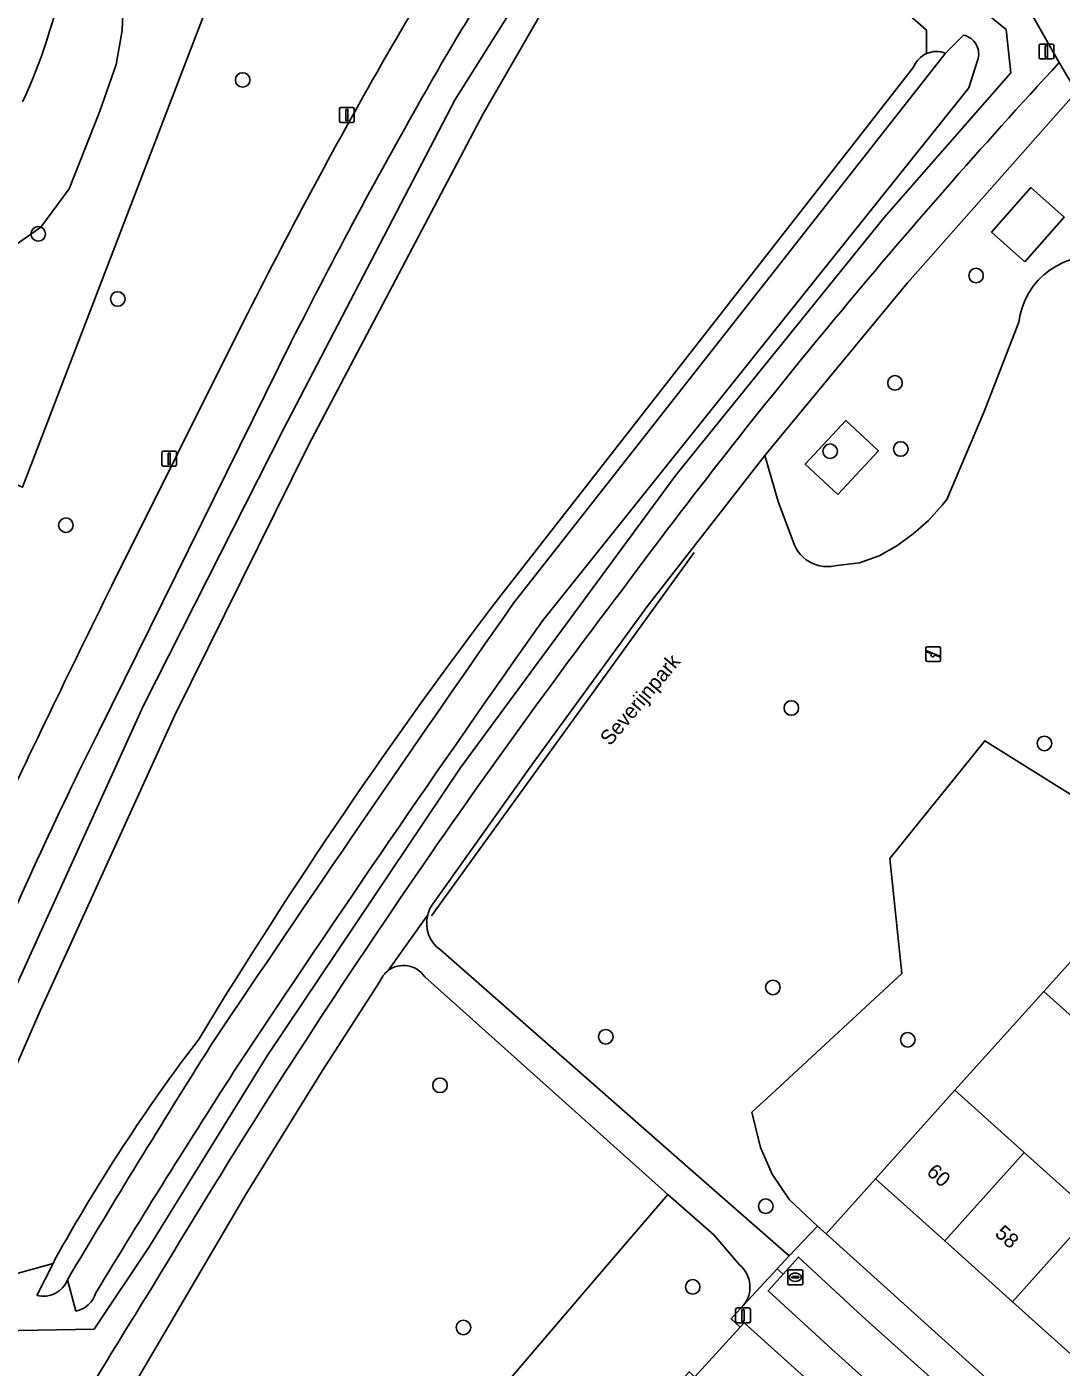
# Model space of a CAD drawing. Extents: x 159039 to 160102, y 381214 to 382524.
# Drawn here: x 159370.3 to 159439.8, y 382088.4 to 382178.5 of the extents above; entities that cross this region are included whole.
import ezdxf

# ---------------------------------------------------------------- set-up
doc = ezdxf.new("R2010")
doc.units = 0
for name, color, linetype in [('IMGEO_Boom', 7, 'Continuous'), ('IMGEO_Erf', 7, 'Continuous'), ('IMGEO_Fietspad_gesloten', 7, 'Continuous'), ('IMGEO_Fietspad_open', 7, 'Continuous'), ('IMGEO_Groenvoorziening', 7, 'Continuous'), ('IMGEO_Hek', 7, 'Continuous'), ('IMGEO_Lichtmast', 7, 'Continuous'), ('IMGEO_Meer_plas_ven_vijver', 7, 'Continuous'), ('IMGEO_Oever', 7, 'Continuous'), ('IMGEO_Openbare_ruimte_label', 7, 'Continuous'), ('IMGEO_Pand', 7, 'Continuous'), ('IMGEO_Pand_nummerreeks', 7, 'Continuous'), ('IMGEO_Rijbaan_lokaal_open', 7, 'Continuous'), ('IMGEO_Rioolput', 7, 'Continuous'), ('IMGEO_Speelvoorziening', 7, 'Continuous'), ('IMGEO_Voetpad_gesloten', 7, 'Continuous'), ('IMGEO_Voetpad_open', 7, 'Continuous'), ('IMGEO_Waterloop', 7, 'Continuous')]:
    doc.layers.add(name, color=color, linetype=linetype)

msp = doc.modelspace()

# ---------------------------------------------------------------- linework, layer by layer
at = {"layer": 'IMGEO_Boom'}
for centre in [(159384.797, 382174.971), (159371.055, 382164.623), (159434.102, 382161.823), (159376.399, 382160.248), (159428.651, 382154.608), (159429.041, 382150.164), (159424.293, 382150.014), (159372.914, 382145.045), (159421.684, 382132.754), (159438.698, 382130.372), (159420.442, 382113.976), (159409.208, 382110.658), (159429.512, 382110.451), (159398.062, 382107.391), (159419.967, 382099.266), (159415.053, 382093.845), (159399.639, 382091.116)]:
    msp.add_circle(centre, 0.489, dxfattribs=at)
at = {"layer": 'IMGEO_Erf'}
for points in [[(159447.332, 382104.853), (159444.401, 382107.483), (159446.182, 382109.469), (159442.855, 382112.454), (159441.607, 382111.063), (159438.669, 382113.699), (159432.686, 382107.057), (159437.336, 382102.884), (159441.895, 382098.793), (159446.455, 382094.7), (159451.014, 382090.609), (159455.662, 382086.437), (159450.321, 382080.486), (159445.673, 382084.658), (159441.114, 382088.749), (159436.554, 382092.841), (159431.994, 382096.933), (159427.345, 382101.105), (159424.019, 382097.413), (159447.998, 382075.782)], [(159442.459, 382069.847), (159418.503, 382091.427), (159418.239, 382091.137), (159415.202, 382087.803), (159419.558, 382083.893), (159424.207, 382079.721), (159428.857, 382075.549), (159433.506, 382071.376), (159438.245, 382067.123), (159432.861, 382061.124), (159428.122, 382065.377), (159423.473, 382069.55), (159418.824, 382073.722), (159414.174, 382077.895)]]:
    msp.add_lwpolyline(points, dxfattribs=at)
at = {"layer": 'IMGEO_Fietspad_gesloten'}
for points in [[(159384.841, 382158.7), (159376.008, 382140.992)], [(159375.118, 382131.186), (159388.062, 382157.36)]]:
    msp.add_lwpolyline(points, dxfattribs=at)
for centre, radius, start, end in [((159545.656, 382089.742), 174.37, 146.13883, 150.3364), ((159526.85, 382101.276), 148.839, 145.75643, 150.62479), ((159732.91, 381983.231), 389.797, 150.35413, 153.24633), ((159715.243, 381992.618), 366.316, 150.26889, 153.27384), ((160147.437, 381758.607), 861, 153.633098, 154.915239), ((159654.193, 381992.43), 311.667, 153.56354, 157.09927)]:
    msp.add_arc(centre, radius, start, end, dxfattribs=at)
at = {"layer": 'IMGEO_Fietspad_open'}
msp.add_lwpolyline([(159434.445, 382185.404), (159439.697, 382176.141), (159440.858, 382174.182)], dxfattribs=at)
at = {"layer": 'IMGEO_Groenvoorziening'}
for points in [[(159392.579, 382206.409), (159369.999, 382147.594), (159365.79, 382149.372), (159363.767, 382150.226), (159359.537, 382139.442), (159361.581, 382138.535), (159365.25, 382136.906), (159366.503, 382136.368), (159366.892, 382135.171), (159361.663, 382115.379)], [(159376.846, 382182.174), (159376.686, 382178.287), (159376.302, 382176.015), (159375.202, 382172.877), (159373.142, 382167.657), (159371.224, 382165.066), (159368.968, 382163.485), (159363.767, 382150.226), (159365.79, 382149.372), (159369.999, 382147.594), (159392.579, 382206.409)], [(159422.353, 382190.549), (159422.734, 382190.305), (159422.983, 382190.468), (159424.514, 382188.415), (159427.144, 382183.833), (159429.09, 382182.451), (159432.379, 382180.645), (159434.583, 382179.615), (159436.124, 382178.366), (159436.429, 382175.447), (159427.914, 382165.716), (159413.925, 382148.417), (159399.408, 382128.719), (159386.451, 382109.386), (159378.514, 382096.541), (159374.803, 382091.012), (159368.466, 382090.901), (159366.281, 382091.313), (159365.922, 382092.134), (159365.812, 382091.888), (159364.063, 382092.583), (159364.104, 382092.669)], [(159370.949, 382093.26), (159372.05, 382095.426), (159367.168, 382094.07), (159365.662, 382092.326), (159365.957, 382092.214), (159365.922, 382092.134), (159366.281, 382091.313), (159368.466, 382090.901), (159374.803, 382091.012), (159378.514, 382096.541), (159386.451, 382109.386), (159399.408, 382128.719), (159413.925, 382148.417), (159427.914, 382165.716), (159436.429, 382175.447), (159436.124, 382178.366), (159434.583, 382179.615), (159432.379, 382180.645), (159429.09, 382182.451), (159427.144, 382183.833), (159424.514, 382188.415), (159424.287, 382188.282), (159422.734, 382190.305), (159422.353, 382190.549)], [(159422.565, 382189.431), (159423.42, 382188.491), (159422.888, 382187.383), (159423.674, 382185.224), (159425.964, 382182.543), (159430.762, 382178.322), (159430.78, 382176.745)], [(159408.268, 382188.263), (159399.088, 382173.666), (159387.535, 382151.506), (159378.119, 382132.921), (159369.246, 382113.396), (159362.92, 382093.152), (159364.104, 382092.669), (159364.204, 382092.878), (159364.739, 382092.675), (159365.059, 382098.418), (159371.182, 382112.41), (159380.224, 382132.238), (159389.22, 382150.415), (159400.964, 382172.686), (159409.272, 382187.122)], [(159364.104, 382092.669), (159362.92, 382093.152), (159369.246, 382113.396), (159378.119, 382132.921), (159387.535, 382151.506), (159399.088, 382173.666), (159408.268, 382188.263)], [(159439.697, 382176.141), (159434.445, 382185.404)], [(159433.268, 382177.987), (159432.043, 382176.774), (159403.013, 382139.809)], [(159432.043, 382176.774), (159433.268, 382177.987)], [(159403.013, 382139.809), (159432.043, 382176.774)], [(159404.959, 382138.622), (159433.607, 382174.444), (159434.204, 382176.286)], [(159434.204, 382176.286), (159433.607, 382174.444), (159404.959, 382138.622)], [(159429.907, 382175.831), (159402.148, 382140.325)], [(159440.858, 382174.182), (159429.499, 382161.337), (159419.901, 382149.722), (159420.807, 382146.642), (159421.896, 382143.703), (159422.011, 382143.477), (159422.148, 382143.264), (159422.308, 382143.066), (159422.487, 382142.886), (159422.684, 382142.726), (159422.896, 382142.588), (159423.122, 382142.472), (159423.359, 382142.381), (159423.603, 382142.314), (159423.854, 382142.274), (159424.107, 382142.26), (159424.361, 382142.273), (159424.611, 382142.312), (159424.747, 382142.345), (159426.257, 382142.505), (159427.588, 382142.981), (159428.774, 382143.66), (159429.882, 382144.459), (159430.901, 382145.37), (159431.819, 382146.382), (159432.128, 382146.776), (159434.651, 382152.693), (159436.985, 382158.687)], [(159436.985, 382158.687), (159437.074, 382159.206), (159437.217, 382159.713), (159437.413, 382160.202), (159437.658, 382160.668), (159437.951, 382161.106), (159438.288, 382161.51), (159438.665, 382161.878), (159439.079, 382162.203), (159439.524, 382162.484), (159439.996, 382162.717), (159440.491, 382162.899), (159440.862, 382162.999), (159442.188, 382163.506), (159443.56, 382163.872), (159444.962, 382164.092), (159446.38, 382164.165), (159447.216, 382164.138)], [(159439.996, 382162.717), (159439.524, 382162.484), (159439.079, 382162.203), (159438.665, 382161.878), (159438.288, 382161.51), (159437.951, 382161.106), (159437.658, 382160.668), (159437.413, 382160.202), (159437.217, 382159.713), (159437.074, 382159.206), (159436.985, 382158.687), (159434.651, 382152.693), (159432.128, 382146.776), (159431.819, 382146.382), (159430.901, 382145.37), (159429.882, 382144.459), (159428.774, 382143.66), (159427.588, 382142.981), (159426.257, 382142.505), (159424.747, 382142.345), (159424.611, 382142.312), (159424.361, 382142.273), (159424.107, 382142.26), (159423.854, 382142.274), (159423.603, 382142.314), (159423.359, 382142.381), (159423.122, 382142.472), (159422.896, 382142.588), (159422.684, 382142.726), (159422.487, 382142.886), (159422.308, 382143.066), (159422.148, 382143.264), (159422.011, 382143.477), (159421.896, 382143.703), (159420.807, 382146.642), (159419.901, 382149.722), (159411.987, 382139.576), (159404.234, 382128.932), (159397.604, 382119.622)], [(159376.008, 382140.992), (159384.841, 382158.7)], [(159388.062, 382157.36), (159375.118, 382131.186)], [(159398.091, 382116.491), (159414.906, 382101.741), (159421.535, 382095.926), (159423.442, 382097.934), (159421.556, 382099.695), (159420.403, 382101.425), (159419.602, 382103.218), (159419.033, 382105.59), (159420.624, 382107.039), (159429.12, 382114.911), (159428.315, 382122.632), (159434.692, 382130.55), (159440.797, 382126.746), (159447.77, 382133.461), (159453.41, 382139.902)], [(159440.797, 382126.746), (159434.692, 382130.55), (159428.315, 382122.632), (159429.12, 382114.911), (159420.624, 382107.039), (159419.033, 382105.59), (159419.602, 382103.218), (159420.403, 382101.425), (159421.556, 382099.695), (159423.442, 382097.934), (159424.019, 382097.413), (159427.345, 382101.105), (159432.686, 382107.057), (159438.669, 382113.699), (159440.485, 382115.723)], [(159408.66, 382094.544), (159413.377, 382100.065), (159397.037, 382114.689)], [(159394.028, 382114.374), (159390.166, 382108.397), (159385.031, 382100.107), (159373.992, 382081.27), (159377.887, 382077.878), (159385.857, 382070.936), (159387.365, 382069.622), (159408.66, 382094.544)], [(159418.2, 382095.331), (159416.462, 382097.35), (159413.377, 382100.065), (159408.66, 382094.544), (159387.365, 382069.622), (159385.857, 382070.936), (159378.221, 382062.169), (159386.063, 382055.21), (159386.52, 382055.672), (159389.076, 382058.583), (159394.457, 382064.578), (159400.284, 382071.006), (159402.2, 382073.142), (159403.989, 382075.135), (159403.541, 382075.537), (159405.385, 382077.591)], [(159372.176, 382095.675), (159372.05, 382095.426), (159370.949, 382093.26)], [(159373.024, 382094.328), (159373.57, 382092.204)], [(159373.57, 382092.204), (159373.024, 382094.328)], [(159405.385, 382077.591), (159409.437, 382082.146), (159414.821, 382088.145), (159415.202, 382087.803), (159418.239, 382091.137), (159417.632, 382091.692), (159418.453, 382092.583)]]:
    msp.add_lwpolyline(points, dxfattribs=at)
for points in [[(159437.391, 382162.754), (159440.035, 382165.752), (159437.786, 382167.734), (159435.143, 382164.737)], [(159437.391, 382162.754), (159435.143, 382164.737), (159437.786, 382167.734), (159440.035, 382165.752)], [(159424.805, 382147.11), (159427.536, 382150.043), (159425.337, 382152.089), (159422.607, 382149.155)], [(159424.805, 382147.11), (159422.607, 382149.155), (159425.337, 382152.089), (159427.536, 382150.043)]]:
    msp.add_lwpolyline(points, close=True, dxfattribs=at)
for centre, radius, start, end in [((159545.656, 382089.742), 174.37, 146.13883, 150.3364), ((159526.85, 382101.276), 148.839, 145.75643, 150.62479), ((159432.983, 382176.722), 1.297, 340.34802, 77.29684), ((159432.983, 382176.722), 1.297, 340.34802, 77.29684), ((159431.448, 382175.233), 1.653, 113.8441, 158.78457), ((159431.447, 382175.233), 1.652, 68.83662, 113.79407), ((159431.447, 382175.233), 1.652, 68.83662, 113.79407), ((159732.91, 381983.231), 389.797, 150.35413, 153.24633), ((159752.486, 381886.865), 426.049, 137.23651, 143.42294), ((159715.243, 381992.618), 366.316, 150.26889, 153.27384), ((160147.437, 381758.607), 861, 153.633098, 154.915239), ((159813.221, 381835.149), 505.669, 142.81805, 149.21492), ((159674.386, 381933.239), 342.05, 142.74049, 148.7828), ((160854.298, 381124.423), 1771.225, 145.0216, 146.188315), ((160854.298, 381124.423), 1771.225, 145.0216, 146.188315), ((160450.54, 381400.124), 1280.085, 144.766282, 146.385082), ((160450.54, 381400.124), 1280.085, 144.766282, 146.385082), ((159654.193, 381992.43), 311.667, 153.56354, 157.09927), ((159399.406, 382118.293), 2.239, 143.58139, 165.40474), ((159399.392, 382118.296), 2.225, 165.38831, 234.21973), ((159395.613, 382113.748), 1.704, 127.40157, 158.45674), ((159395.615, 382113.748), 1.705, 33.4951, 127.43671), ((159478.564, 382036.832), 121.577, 142.69292, 151.05308), ((159941.525, 381757.41), 660.838, 147.749459, 149.347191), ((159941.525, 381757.41), 660.838, 147.749459, 149.347191), ((159889.716, 381782.72), 601.291, 147.160781, 148.885497), ((159889.716, 381782.72), 601.291, 147.160781, 148.885497), ((159416.94, 382093.829), 1.96, 320.51924, 50.0012), ((159702.63, 381890.619), 382.375, 147.87389, 151.49088), ((159371.375, 382094.983), 1.774, 256.11767, 338.35198), ((159371.375, 382094.983), 1.774, 256.11767, 338.35198), ((159373.191, 382093.987), 1.823, 281.99129, 342.44267), ((159373.191, 382093.987), 1.823, 281.99129, 342.44267)]:
    msp.add_arc(centre, radius, start, end, dxfattribs=at)
at = {"layer": 'IMGEO_Hek'}
msp.add_lwpolyline([(159397.488, 382118.797), (159415.14, 382143.214)], dxfattribs=at)
at = {"layer": 'IMGEO_Lichtmast'}
for p, q in [((159438.337, 382176.487), (159438.337, 382177.287)), ((159438.337, 382177.287), (159438.337, 382176.487)), ((159438.437, 382177.387), (159439.227, 382177.387)), ((159439.227, 382177.387), (159438.437, 382177.387)), ((159439.327, 382177.287), (159439.327, 382176.487)), ((159439.327, 382176.487), (159439.327, 382177.287)), ((159439.227, 382176.387), (159438.437, 382176.387)), ((159438.437, 382176.387), (159439.227, 382176.387)), ((159391.307, 382172.221), (159391.307, 382173.021)), ((159391.307, 382173.021), (159391.307, 382172.221)), ((159391.407, 382173.121), (159392.197, 382173.121)), ((159392.197, 382173.121), (159391.407, 382173.121)), ((159392.297, 382173.021), (159392.297, 382172.221)), ((159392.297, 382172.221), (159392.297, 382173.021)), ((159392.197, 382172.121), (159391.407, 382172.121)), ((159391.407, 382172.121), (159392.197, 382172.121)), ((159379.363, 382149.118), (159379.363, 382149.918)), ((159379.363, 382149.918), (159379.363, 382149.118)), ((159379.463, 382150.018), (159380.253, 382150.018)), ((159380.253, 382150.018), (159379.463, 382150.018)), ((159380.353, 382149.918), (159380.353, 382149.118)), ((159380.353, 382149.118), (159380.353, 382149.918)), ((159380.253, 382149.018), (159379.463, 382149.018)), ((159379.463, 382149.018), (159380.253, 382149.018)), ((159417.939, 382091.526), (159417.939, 382092.326)), ((159417.939, 382092.326), (159417.939, 382091.526)), ((159418.039, 382092.426), (159418.829, 382092.426)), ((159418.829, 382092.426), (159418.039, 382092.426)), ((159418.929, 382092.326), (159418.929, 382091.526)), ((159418.929, 382091.526), (159418.929, 382092.326)), ((159418.829, 382091.426), (159418.039, 382091.426)), ((159418.039, 382091.426), (159418.829, 382091.426))]:
    msp.add_line(p, q, dxfattribs=at)
for points in [[(159438.757, 382177.262), (159438.907, 382177.262), (159438.907, 382176.512), (159438.757, 382176.512), (159438.757, 382177.262)], [(159391.727, 382172.996), (159391.877, 382172.996), (159391.877, 382172.246), (159391.727, 382172.246), (159391.727, 382172.996)], [(159379.783, 382149.893), (159379.933, 382149.893), (159379.933, 382149.143), (159379.783, 382149.143), (159379.783, 382149.893)], [(159418.359, 382092.301), (159418.509, 382092.301), (159418.509, 382091.551), (159418.359, 382091.551), (159418.359, 382092.301)]]:
    msp.add_lwpolyline(points, dxfattribs=at)
for centre, start, end in [((159438.437, 382177.287), 90, 180), ((159438.437, 382177.287), 90, 180), ((159439.227, 382177.287), 0, 90), ((159439.227, 382177.287), 360, 90), ((159438.437, 382176.487), 180, 270), ((159438.437, 382176.487), 180, 270), ((159439.227, 382176.487), 270, 0), ((159439.227, 382176.487), 270, 0), ((159391.407, 382173.021), 90, 180), ((159391.407, 382173.021), 90, 180), ((159392.197, 382173.021), 0, 90), ((159392.197, 382173.021), 360, 90), ((159391.407, 382172.221), 180, 270), ((159391.407, 382172.221), 180, 270), ((159392.197, 382172.221), 270, 0), ((159392.197, 382172.221), 270, 0), ((159379.463, 382149.918), 90, 180), ((159379.463, 382149.918), 90, 180), ((159380.253, 382149.918), 0, 90), ((159380.253, 382149.918), 360, 90), ((159379.463, 382149.118), 180, 270), ((159379.463, 382149.118), 180, 270), ((159380.253, 382149.118), 270, 0), ((159380.253, 382149.118), 270, 0), ((159418.039, 382092.326), 90, 180), ((159418.039, 382092.326), 90, 180), ((159418.829, 382092.326), 0, 90), ((159418.829, 382092.326), 360, 90), ((159418.039, 382091.526), 180, 270), ((159418.039, 382091.526), 180, 270), ((159418.829, 382091.526), 270, 0), ((159418.829, 382091.526), 270, 0)]:
    msp.add_arc(centre, 0.1, start, end, dxfattribs=at)
at = {"layer": 'IMGEO_Meer_plas_ven_vijver'}
for points in [[(159430.78, 382176.745), (159430.762, 382178.322), (159425.964, 382182.543), (159423.674, 382185.224), (159422.888, 382187.383), (159423.42, 382188.491), (159422.565, 382189.431)], [(159409.272, 382187.122), (159400.964, 382172.686), (159389.22, 382150.415), (159380.224, 382132.238), (159371.182, 382112.41), (159365.059, 382098.418), (159364.739, 382092.675), (159365.662, 382092.326), (159367.168, 382094.07), (159372.05, 382095.426), (159372.176, 382095.675)], [(159402.148, 382140.325), (159429.907, 382175.831)]]:
    msp.add_lwpolyline(points, dxfattribs=at)
for centre, radius, start, end in [((159431.448, 382175.233), 1.653, 113.8441, 158.78457), ((159674.386, 381933.239), 342.05, 142.74049, 148.7828), ((159478.564, 382036.832), 121.577, 142.69292, 151.05308)]:
    msp.add_arc(centre, radius, start, end, dxfattribs=at)
at = {"layer": 'IMGEO_Oever'}
msp.add_lwpolyline([(159329.64, 382062.981), (159336.5, 382081.036), (159338.599, 382083.068), (159340.207, 382084.766), (159341.09, 382085.551), (159342.397, 382086.714), (159343.395, 382090.494), (159343.294, 382091.297), (159343.198, 382092.049), (159342.522, 382092.718), (159341.643, 382093.428), (159341.595, 382094.275), (159351.487, 382118.919), (159359.537, 382139.442), (159363.767, 382150.226), (159368.968, 382163.485), (159371.224, 382165.066), (159373.142, 382167.657), (159375.202, 382172.877), (159376.302, 382176.015), (159376.686, 382178.287), (159376.846, 382182.174)], dxfattribs=at)
msp.add_arc((159335.714, 382189.399), 37.792, 335.1341, 348.80944, dxfattribs=at)
at = {"layer": 'IMGEO_Pand'}
for points in [[(159440.485, 382115.723), (159438.669, 382113.699), (159441.607, 382111.063), (159442.855, 382112.454), (159443.423, 382113.087)], [(159437.336, 382102.884), (159432.686, 382107.057), (159427.345, 382101.105), (159431.994, 382096.933)], [(159437.336, 382102.884), (159431.994, 382096.933), (159436.554, 382092.841), (159441.895, 382098.793)], [(159441.895, 382098.793), (159436.554, 382092.841), (159441.114, 382088.749), (159446.455, 382094.7)]]:
    msp.add_lwpolyline(points, close=True, dxfattribs=at)
at = {"layer": 'IMGEO_Rijbaan_lokaal_open'}
msp.add_lwpolyline([(159426.476, 382091.859), (159422.172, 382095.85), (159421.139, 382094.706), (159420.122, 382093.578), (159424.405, 382089.668), (159432.474, 382082.409), (159445.513, 382070.713), (159447.544, 382072.913), (159439.286, 382080.355)], close=True, dxfattribs=at)
at = {"layer": 'IMGEO_Rioolput'}
for p, q in [((159421.448, 382094.064), (159421.448, 382094.916)), ((159421.523, 382094.99), (159422.375, 382094.99)), ((159421.936, 382094.77), (159421.961, 382094.77)), ((159422.449, 382094.916), (159422.449, 382094.064)), ((159422.375, 382093.99), (159421.523, 382093.99)), ((159421.707, 382094.484), (159421.707, 382094.496)), ((159422.145, 382094.447), (159421.747, 382094.447)), ((159421.75, 382094.533), (159422.148, 382094.533)), ((159421.959, 382094.21), (159421.934, 382094.21)), ((159422.191, 382094.496), (159422.191, 382094.484))]:
    msp.add_line(p, q, dxfattribs=at)
for points in [[(159421.448, 382094.064), (159421.448, 382094.916)], [(159421.523, 382094.99), (159422.375, 382094.99)], [(159422.449, 382094.916), (159422.449, 382094.064)], [(159422.375, 382093.99), (159421.523, 382093.99)]]:
    msp.add_lwpolyline(points, dxfattribs=at)
for centre, radius, start, end in [((159421.525, 382094.914), 0.0765, 91.55205, 178.44795), ((159421.525, 382094.914), 0.0765, 91.55205, 178.44795), ((159422.373, 382094.914), 0.0765, 1.55205, 88.44795), ((159422.373, 382094.914), 0.0765, 1.55205, 88.44795), ((159421.525, 382094.066), 0.0765, 181.55205, 268.44795), ((159421.525, 382094.066), 0.0765, 181.55205, 268.44795), ((159421.747, 382094.493), 0.0403, 85.87752, 175.75265), ((159421.744, 382094.483), 0.0366, 178.93798, 274.71019), ((159422.148, 382094.49), 0.043, 264.86636, 352.45326), ((159422.152, 382094.495), 0.0386, 1.73085, 96.63898), ((159422.373, 382094.066), 0.0765, 271.55205, 358.44795), ((159422.373, 382094.066), 0.0765, 271.55205, 358.44795)]:
    msp.add_arc(centre, radius, start, end, dxfattribs=at)
for centre, major_axis, ratio, start_param, end_param in [((159421.935, 382094.49), (-0.387, 0.002), 0.722429, 4.712389, 7.853982), ((159421.96, 382094.49), (-0.39, 0.002), 0.717154, 1.570796, 4.712389)]:
    msp.add_ellipse(centre, major_axis=major_axis, ratio=ratio, start_param=start_param, end_param=end_param, dxfattribs=at)
at = {"layer": 'IMGEO_Speelvoorziening'}
for p, q in [((159430.728, 382135.975), (159430.728, 382136.775)), ((159430.728, 382136.775), (159430.728, 382135.975)), ((159431.111, 382136.403), (159430.772, 382136.54)), ((159430.797, 382136.6), (159431.673, 382136.247)), ((159430.828, 382136.875), (159431.618, 382136.875)), ((159431.618, 382136.875), (159430.828, 382136.875)), ((159431.649, 382136.187), (159431.309, 382136.324)), ((159431.718, 382136.775), (159431.718, 382135.975)), ((159431.718, 382135.975), (159431.718, 382136.775)), ((159431.618, 382135.875), (159430.828, 382135.875)), ((159430.828, 382135.875), (159431.618, 382135.875))]:
    msp.add_line(p, q, dxfattribs=at)
for centre, radius, start, end in [((159430.828, 382136.775), 0.1, 90, 180), ((159430.828, 382136.775), 0.1, 90, 180), ((159430.785, 382136.57), 0.0327, 68.07798, 248.07798), ((159431.19, 382136.313), 0.12, 130.99278, 5.16318), ((159431.618, 382136.775), 0.1, 0, 90), ((159431.618, 382136.775), 0.1, 360, 90), ((159431.661, 382136.217), 0.0327, 248.07798, 68.07798), ((159430.828, 382135.975), 0.1, 180, 270), ((159430.828, 382135.975), 0.1, 180, 270), ((159431.618, 382135.975), 0.1, 270, 0), ((159431.618, 382135.975), 0.1, 270, 0)]:
    msp.add_arc(centre, radius, start, end, dxfattribs=at)
at = {"layer": 'IMGEO_Voetpad_gesloten'}
for points in [[(159397.604, 382119.622), (159404.234, 382128.932), (159411.987, 382139.576), (159419.901, 382149.722), (159429.499, 382161.337), (159440.858, 382174.182), (159439.697, 382176.141)], [(159394.578, 382115.102), (159397.239, 382118.857)], [(159397.239, 382118.857), (159394.578, 382115.102)], [(159418.453, 382092.583), (159420.742, 382095.065), (159421.535, 382095.926), (159414.906, 382101.741), (159398.091, 382116.491)], [(159397.037, 382114.689), (159413.377, 382100.065), (159416.462, 382097.35), (159418.2, 382095.331)], [(159368.975, 382072.218), (159373.992, 382081.27), (159385.031, 382100.107), (159390.166, 382108.397), (159394.028, 382114.374)]]:
    msp.add_lwpolyline(points, dxfattribs=at)
for centre, radius, start, end in [((159752.486, 381886.865), 426.049, 137.23651, 143.42294), ((159813.221, 381835.149), 505.669, 142.81805, 149.21492), ((159399.406, 382118.293), 2.239, 143.58139, 165.40474), ((159399.392, 382118.296), 2.225, 165.38831, 234.21973), ((159395.613, 382113.748), 1.704, 127.40157, 158.45674), ((159395.615, 382113.748), 1.705, 33.4951, 127.43671), ((159416.94, 382093.829), 1.96, 320.51924, 50.0012), ((159702.63, 381890.619), 382.375, 147.87389, 151.49088)]:
    msp.add_arc(centre, radius, start, end, dxfattribs=at)
at = {"layer": 'IMGEO_Voetpad_open'}
for points in [[(159424.019, 382097.413), (159423.442, 382097.934), (159421.535, 382095.926), (159420.742, 382095.065), (159421.139, 382094.706), (159422.172, 382095.85), (159426.476, 382091.859), (159439.286, 382080.355), (159447.544, 382072.913), (159449.93, 382075.598)], [(159447.998, 382075.782), (159424.019, 382097.413)], [(159432.474, 382082.409), (159424.405, 382089.668), (159420.122, 382093.578), (159421.139, 382094.706), (159420.742, 382095.065), (159418.453, 382092.583), (159417.632, 382091.692), (159418.239, 382091.137), (159418.503, 382091.427), (159442.459, 382069.847)]]:
    msp.add_lwpolyline(points, dxfattribs=at)
at = {"layer": 'IMGEO_Waterloop'}
msp.add_arc((159335.714, 382189.399), 37.792, 335.1341, 348.80944, dxfattribs=at)

# ---------------------------------------------------------------- texts
at = {"layer": 'IMGEO_Openbare_ruimte_label'}
msp.add_text('Severijnpark', height=1, rotation=49.90832, dxfattribs=at).set_placement((159409.498, 382130.158))
at = {"layer": 'IMGEO_Pand_nummerreeks'}
for s, p in [('60', (159430.713, 382101.468)), ('58', (159435.308, 382097.345))]:
    msp.add_text(s, height=1, rotation=318.09473, dxfattribs=at).set_placement(p)

doc.saveas('drawing.dxf')
